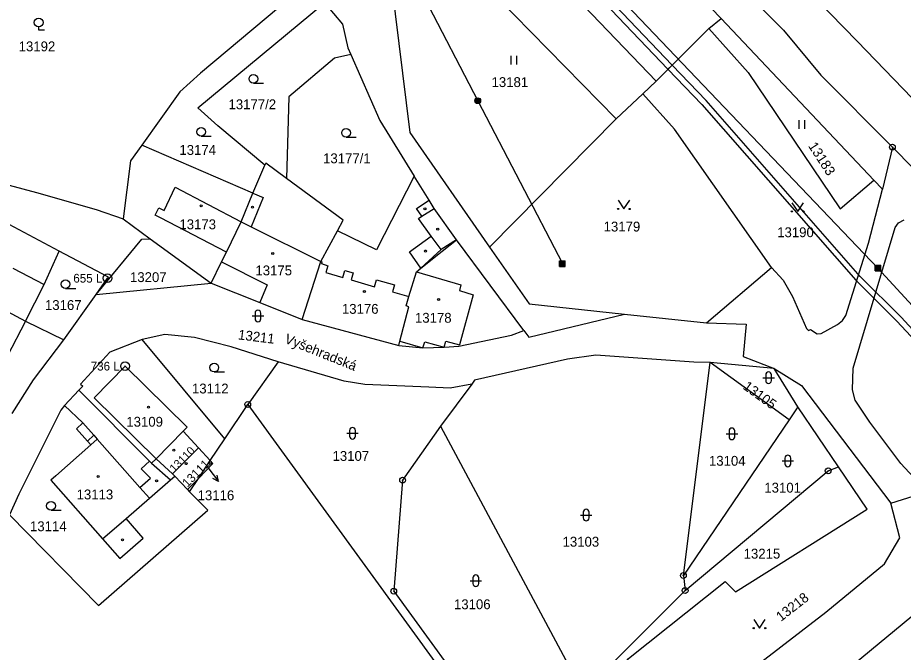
# Model space of a CAD drawing. Extents: x -821458 to -820266, y -1071458 to -1069826.
# Drawn here: x -820498 to -820345.1, y -1071261.9 to -1071152.4 of the extents above; entities that cross this region are included whole.
import ezdxf

# ---------------------------------------------------------------- set-up
doc = ezdxf.new("R2010")
doc.units = 0
for name, color, linetype in [('Vrstva 1', 7, 'Continuous'), ('Vrstva 13', 7, 'Continuous'), ('Vrstva 2', 7, 'Continuous'), ('Vrstva 3', 7, 'Continuous'), ('Vrstva 4', 7, 'Continuous'), ('Vrstva 5', 7, 'Continuous'), ('Vrstva 6', 7, 'Continuous'), ('Vrstva 7', 7, 'Continuous'), ('Vrstva 8', 7, 'Continuous')]:
    doc.layers.add(name, color=color, linetype=linetype)

msp = doc.modelspace()

# ---------------------------------------------------------------- linework, layer by layer
at = {"layer": 'Vrstva 1'}
for p, q in [((-820376.56, -1071152.47), (-820404.04, -1071123.96)), ((-820394.7, -1071169.8), (-820435.54, -1071128.19)), ((-820416.32, -1071133.58), (-820387.8, -1071163.3)), ((-820378.7, -1071154.2), (-820376.56, -1071152.47)), ((-820350.18, -1071180.42), (-820376.56, -1071152.47)), ((-820387.8, -1071163.3), (-820378.7, -1071154.2)), ((-820390.1, -1071165.5), (-820387.8, -1071163.3)), ((-820390.1, -1071165.5), (-820394.7, -1071169.8)), ((-820394.7, -1071169.8), (-820416.56, -1071192)), ((-820457.41, -1071182.67), (-820476.62, -1071174.38)), ((-820347, -1071174.7), (-820348.72, -1071181.96)), ((-820457.41, -1071182.67), (-820455.36, -1071177.84)), ((-820348.72, -1071181.96), (-820350.18, -1071180.42)), ((-820479.84, -1071187.11), (-820475.14, -1071190.53)), ((-820475.14, -1071190.53), (-820464.62, -1071198.17)), ((-820410.65, -1071206.34), (-820422.27, -1071190.7)), ((-820379.11, -1071205.04), (-820367.9, -1071195.5)), ((-820367.9, -1071195.5), (-820365.84, -1071197.65)), ((-820510.83, -1071197.24), (-820496.66, -1071204.76)), ((-820484.47, -1071200.14), (-820464.62, -1071198.17)), ((-820490.07, -1071207.98), (-820484.47, -1071200.14)), ((-820496.66, -1071204.76), (-820490.07, -1071207.98)), ((-820448.89, -1071204.48), (-820432.24, -1071208.93)), ((-820393.23, -1071203.55), (-820379.11, -1071205.04)), ((-820462.25, -1071225.04), (-820476.55, -1071207.91)), ((-820453.05, -1071211.75), (-820458.31, -1071219.13)), ((-820383.08, -1071248.67), (-820378.48, -1071211.88)), ((-820364.84, -1071221.76), (-820378.48, -1071211.88)), ((-820367.43, -1071212.95), (-820378.48, -1071211.88)), ((-820363.33, -1071219.52), (-820367.43, -1071212.95)), ((-820487.46, -1071216.64), (-820489.97, -1071219.33)), ((-820419.6, -1071215.61), (-820425.02, -1071222.9)), ((-820462.25, -1071225.04), (-820458.31, -1071219.13)), ((-820458.31, -1071219.13), (-820414.04, -1071279.95)), ((-820363.33, -1071219.52), (-820364.84, -1071221.76)), ((-820356.32, -1071229.9), (-820363.33, -1071219.52)), ((-820364.84, -1071221.76), (-820383.08, -1071248.67)), ((-820464.77, -1071228.82), (-820462.25, -1071225.04)), ((-820471.3, -1071231.09), (-820466.83, -1071226.61)), ((-820466.83, -1071226.61), (-820464.77, -1071228.82)), ((-820474.13, -1071228.51), (-820471.3, -1071231.09)), ((-820466.83, -1071231.91), (-820464.77, -1071228.82)), ((-820471.3, -1071231.09), (-820470.87, -1071231.52)), ((-820468.35, -1071234.19), (-820466.83, -1071231.91)), ((-820383.08, -1071248.67), (-820382.79, -1071251.27))]:
    msp.add_line(p, q, dxfattribs=at)
for points in [[(-820575.41, -1070898.25), (-820570.53, -1070910.66), (-820562.59, -1070929.03), (-820552.69, -1070946.67), (-820539.84, -1070967.11), (-820528.16, -1070983.62), (-820516.84, -1071000.47), (-820503.22, -1071015.12), (-820488.13, -1071031.13), (-820440.56, -1071079.73), (-820404.7, -1071115.79), (-820365.81, -1071154.53), (-820359.33, -1071162.29), (-820347, -1071174.7)], [(-820437.25, -1071144.25), (-820433.5, -1071146.49), (-820430.3, -1071172.18), (-820416.56, -1071192)], [(-820448.39, -1071146.76), (-820466.46, -1071161.95), (-820470.02, -1071165.17), (-820476.62, -1071174.38)], [(-820455.36, -1071177.84), (-820463.46, -1071171), (-820466.9, -1071167.9), (-820445.03, -1071149.78)], [(-820445.03, -1071149.78), (-820441.94, -1071153.46), (-820441.02, -1071157.59), (-820440.53, -1071158.71)], [(-820340.44, -1071169.52), (-820353.06, -1071156.4), (-820360.13, -1071149.18)], [(-820378.7, -1071154.2), (-820371.9, -1071161.8), (-820355.99, -1071185.37), (-820350.18, -1071180.42)], [(-820440.53, -1071158.71), (-820443.34, -1071159.32), (-820451.23, -1071166.02), (-820451.64, -1071180.1)], [(-820440.53, -1071158.71), (-820435.49, -1071170.13), (-820429.56, -1071179.71)], [(-820539.3, -1071159.45), (-820522.31, -1071172.09), (-820517.39, -1071175), (-820505.17, -1071179.75), (-820494.77, -1071182.54), (-820484.47, -1071185.46), (-820479.84, -1071187.11)], [(-820367.9, -1071195.5), (-820384.6, -1071171.6), (-820390.1, -1071165.5)], [(-820476.62, -1071174.38), (-820478.54, -1071177.06), (-820479.84, -1071187.11)], [(-820347, -1071174.7), (-820346.49, -1071175.21), (-820336.47, -1071185.46)], [(-820451.64, -1071180.1), (-820455.2, -1071177.47), (-820455.36, -1071177.84)], [(-820442.83, -1071189.15), (-820441.85, -1071187.34), (-820451.64, -1071180.1)], [(-820429.56, -1071179.71), (-820436.09, -1071192.46), (-820442.83, -1071189.15)], [(-820422.27, -1071190.7), (-820426.11, -1071185.29), (-820427.01, -1071183.84), (-820429.56, -1071179.71)], [(-820464.62, -1071198.17), (-820462.84, -1071194.51), (-820461.97, -1071192.83), (-820459.47, -1071187.61), (-820457.41, -1071182.67)], [(-820365.84, -1071197.65), (-820364.24, -1071200.52), (-820361.84, -1071206), (-820361.48, -1071206.37), (-820361.14, -1071206.21), (-820360, -1071206.96), (-820359.28, -1071206.87), (-820356.47, -1071205.32), (-820355.61, -1071204.65), (-820355.02, -1071203.75), (-820351.14, -1071191.31), (-820348.72, -1071181.96)], [(-820490.89, -1071192.65), (-820500.39, -1071187.63), (-820501.57, -1071187.01), (-820505.26, -1071185.93)], [(-820343.38, -1071231.68), (-820345.52, -1071229.33), (-820350.87, -1071222.17), (-820353.43, -1071218.41), (-820353.9, -1071216.58), (-820353.77, -1071212.85), (-820346.53, -1071188.58), (-820345.92, -1071187.79), (-820344.96, -1071187.27)], [(-820448.89, -1071204.48), (-820445.67, -1071194.43), (-820442.83, -1071189.15)], [(-820484.47, -1071200.14), (-820476.61, -1071190.6), (-820475.14, -1071190.53)], [(-820432.24, -1071208.93), (-820432.05, -1071208.22), (-820430.47, -1071202.26), (-820430.95, -1071202.12), (-820430.47, -1071200.52), (-820429.19, -1071196.22), (-820428.41, -1071195.6), (-820424.73, -1071192.67), (-820422.27, -1071190.7)], [(-820496.66, -1071204.76), (-820493.45, -1071198.44), (-820490.89, -1071192.65)], [(-820484.47, -1071200.14), (-820482.5, -1071197.34), (-820482.36, -1071197.15), (-820490.89, -1071192.65)], [(-820416.56, -1071192), (-820409.72, -1071201.74), (-820393.23, -1071203.55)], [(-820464.62, -1071198.17), (-820456.22, -1071201.54), (-820448.89, -1071204.48)], [(-820410.65, -1071206.34), (-820409.78, -1071207.51), (-820393.23, -1071203.55)], [(-820432.24, -1071208.93), (-820428.06, -1071209.38), (-820424.39, -1071209.25), (-820421.85, -1071209.06), (-820412.78, -1071207.15), (-820410.65, -1071206.34)], [(-820379.11, -1071205.04), (-820372.25, -1071205.26), (-820372.78, -1071210.85), (-820367.43, -1071212.95)], [(-820476.55, -1071207.91), (-820482.13, -1071210.12), (-820487.19, -1071215.63), (-820486.81, -1071215.95), (-820487.46, -1071216.64)], [(-820453.05, -1071211.75), (-820461.2, -1071209.17), (-820467.5, -1071207.56), (-820472.6, -1071207.05), (-820476.55, -1071207.91)], [(-820499.01, -1071220.67), (-820495.3, -1071214.89), (-820490.07, -1071207.98)], [(-820378.48, -1071211.88), (-820381.28, -1071211.81), (-820398.21, -1071210.6), (-820403.09, -1071211.33), (-820419.16, -1071214.95), (-820419.6, -1071215.61)], [(-820419.6, -1071215.61), (-820423.38, -1071216.29), (-820427.04, -1071216.16), (-820438.11, -1071215.68), (-820441.64, -1071215.11), (-820453.05, -1071211.75)], [(-820367.43, -1071212.95), (-820362.68, -1071215.85), (-820347.25, -1071236.15)], [(-820487.46, -1071216.64), (-820475.27, -1071228.92), (-820474.9, -1071229.29), (-820474.13, -1071228.51)], [(-820489.97, -1071219.33), (-820490.59, -1071220.12), (-820497.82, -1071234.6), (-820499.47, -1071238.21)], [(-820489.97, -1071219.33), (-820486.77, -1071222.33), (-820487.9, -1071223.33), (-820486, -1071225.47), (-820485.43, -1071226.12), (-820491.46, -1071231.44), (-820492.3, -1071232.18), (-820483.36, -1071242.35), (-820480.4, -1071245.73), (-820476.37, -1071242.19), (-820479.31, -1071238.83), (-820475.27, -1071235.32), (-820471.62, -1071232.17), (-820470.87, -1071231.52)], [(-820425.02, -1071222.9), (-820431.56, -1071232.21), (-820433.1, -1071251.37), (-820417.36, -1071272.99), (-820410.98, -1071267.78), (-820405.1, -1071274.59)], [(-820425.02, -1071222.9), (-820400.38, -1071268.87), (-820398.96, -1071271.52)], [(-820474.13, -1071228.51), (-820469.47, -1071223.77), (-820466.83, -1071226.61)], [(-820466.83, -1071231.91), (-820464.31, -1071229.31), (-820464.77, -1071228.82)], [(-820399.7, -1071273.16), (-820392.58, -1071262.99), (-820375.9, -1071249.7), (-820374.1, -1071251.5), (-820351.38, -1071237.19), (-820356.32, -1071229.9)], [(-820382.79, -1071251.27), (-820358.08, -1071230.59), (-820356.32, -1071229.9)], [(-820470.87, -1071231.52), (-820468.7, -1071233.83), (-820468.35, -1071234.19)], [(-820347.25, -1071236.15), (-820342.32, -1071234.63), (-820337.67, -1071234.87), (-820334.05, -1071232.87)], [(-820499.47, -1071238.21), (-820484.08, -1071253.85), (-820465.21, -1071237.36), (-820468.35, -1071234.19)], [(-820402.91, -1071290.65), (-820398.95, -1071286.93), (-820388.19, -1071277.72), (-820379.51, -1071270.89), (-820370.53, -1071264.24), (-820358.49, -1071254.97), (-820348.34, -1071246.63), (-820345.74, -1071242.13), (-820347.25, -1071236.15)], [(-820326.72, -1071239.67), (-820331.97, -1071245.01), (-820342.31, -1071254.65), (-820353.61, -1071263.96), (-820360.02, -1071268.97), (-820360.98, -1071270.3), (-820361.65, -1071272.32), (-820361.24, -1071273.9), (-820360.23, -1071275.23)], [(-820398.96, -1071271.52), (-820395.64, -1071264.1), (-820382.79, -1071251.27)]]:
    msp.add_lwpolyline(points, dxfattribs=at)
at = {"layer": 'Vrstva 13'}
msp.add_lwpolyline([(-820413.93, -1071131.71), (-820385.75, -1071161.25), (-820385.03, -1071160.53), (-820413.14, -1071131.09)], close=True, dxfattribs=at)
msp.add_lwpolyline([(-820341.51, -1071208.35), (-820345.51, -1071204.08), (-820352.56, -1071197.02), (-820379.18, -1071166.67), (-820385.03, -1071160.53), (-820385.75, -1071161.25), (-820379.92, -1071167.35), (-820353.3, -1071197.7), (-820346.23, -1071204.78), (-820342.21, -1071209.05)], dxfattribs=at)
at = {"layer": 'Vrstva 3'}
for p, q in [((-820494.41, -1071153.93), (-820494.41, -1071154.43)), ((-820494.41, -1071154.43), (-820493.41, -1071154.43)), ((-820412.85, -1071160.44), (-820412.85, -1071158.94)), ((-820411.85, -1071160.44), (-820411.85, -1071158.94)), ((-820457.34, -1071163.65), (-820455.59, -1071163.65)), ((-820363.1, -1071171.56), (-820363.1, -1071170.06)), ((-820362.1, -1071171.56), (-820362.1, -1071170.06)), ((-820466.35, -1071172.81), (-820464.6, -1071172.81)), ((-820441.34, -1071172.98), (-820439.59, -1071172.98)), ((-820489.76, -1071199.1), (-820488.01, -1071199.1)), ((-820457.04, -1071203.35), (-820457.04, -1071204.35)), ((-820456.04, -1071204.35), (-820456.04, -1071203.35)), ((-820457.54, -1071203.85), (-820455.54, -1071203.85)), ((-820464.09, -1071213.52), (-820462.34, -1071213.52)), ((-820368.88, -1071214.01), (-820368.88, -1071215.01)), ((-820367.88, -1071215.01), (-820367.88, -1071214.01)), ((-820369.38, -1071214.51), (-820367.38, -1071214.51)), ((-820441.22, -1071224.1), (-820439.22, -1071224.1)), ((-820440.72, -1071223.6), (-820440.72, -1071224.6)), ((-820439.72, -1071224.6), (-820439.72, -1071223.6)), ((-820375.71, -1071224.2), (-820373.71, -1071224.2)), ((-820375.21, -1071223.7), (-820375.21, -1071224.7)), ((-820374.21, -1071224.7), (-820374.21, -1071223.7)), ((-820366.05, -1071228.88), (-820364.05, -1071228.88)), ((-820365.55, -1071228.38), (-820365.55, -1071229.38)), ((-820364.55, -1071229.38), (-820364.55, -1071228.38)), ((-820492.28, -1071237.39), (-820490.53, -1071237.39)), ((-820400.88, -1071238.23), (-820398.88, -1071238.23)), ((-820400.38, -1071237.73), (-820400.38, -1071238.73)), ((-820399.38, -1071238.73), (-820399.38, -1071237.73)), ((-820419.42, -1071249.06), (-820419.42, -1071250.06)), ((-820418.42, -1071250.06), (-820418.42, -1071249.06)), ((-820419.92, -1071249.56), (-820417.92, -1071249.56))]:
    msp.add_line(p, q, dxfattribs=at)
for points in [[(-820394.36, -1071183.88), (-820393.36, -1071185.38), (-820392.36, -1071183.88)], [(-820364.35, -1071184.3), (-820363.35, -1071185.8), (-820362.35, -1071184.3)], [(-820370.94, -1071256.24), (-820369.94, -1071257.74), (-820368.94, -1071256.24)]]:
    msp.add_lwpolyline(points, dxfattribs=at)
for centre, radius in [((-820494.41, -1071153.18), 0.75), ((-820457.34, -1071162.9), 0.75), ((-820466.35, -1071172.06), 0.75), ((-820441.34, -1071172.23), 0.75), ((-820394.36, -1071185.38), 0.1), ((-820392.36, -1071185.38), 0.1), ((-820364.35, -1071185.8), 0.1), ((-820362.35, -1071185.8), 0.1), ((-820489.76, -1071198.35), 0.75), ((-820464.09, -1071212.77), 0.75), ((-820492.28, -1071236.64), 0.75), ((-820370.94, -1071257.74), 0.1), ((-820368.94, -1071257.74), 0.1)]:
    msp.add_circle(centre, radius, dxfattribs=at)
for centre, start, end in [((-820456.54, -1071203.35), 0, 180), ((-820456.54, -1071204.35), 180, 359.9879), ((-820368.38, -1071214.01), 0, 180), ((-820368.38, -1071215.01), 180, 359.9879), ((-820440.22, -1071223.6), 0, 180), ((-820374.71, -1071223.7), 0, 180), ((-820440.22, -1071224.6), 180, 359.9879), ((-820374.71, -1071224.7), 180, 359.9879), ((-820365.05, -1071228.38), 0, 180), ((-820365.05, -1071229.38), 180, 359.9879), ((-820399.88, -1071237.73), 0, 180), ((-820399.88, -1071238.73), 180, 359.9879), ((-820418.92, -1071249.06), 0, 180), ((-820418.92, -1071250.06), 180, 359.9879)]:
    msp.add_arc(centre, 0.5, start, end, dxfattribs=at)
at = {"layer": 'Vrstva 4'}
for p, q in [((-820472.76, -1071185.64), (-820470.82, -1071181.61)), ((-820470.82, -1071181.61), (-820459.47, -1071187.61)), ((-820455.64, -1071183.41), (-820457.74, -1071188.47)), ((-820457.41, -1071182.67), (-820455.64, -1071183.41)), ((-820429.17, -1071185.31), (-820427.01, -1071183.84)), ((-820474.27, -1071186.47), (-820473.66, -1071185.2)), ((-820473.37, -1071186.9), (-820474.27, -1071186.47)), ((-820473.66, -1071185.2), (-820472.76, -1071185.64)), ((-820428.23, -1071186.62), (-820429.17, -1071185.31)), ((-820428.23, -1071186.62), (-820426.11, -1071185.29)), ((-820461.97, -1071192.83), (-820473.37, -1071186.9)), ((-820459.47, -1071187.61), (-820457.74, -1071188.47)), ((-820428.81, -1071187.03), (-820428.23, -1071186.62)), ((-820426.62, -1071190.06), (-820428.81, -1071187.03)), ((-820457.74, -1071188.47), (-820445.67, -1071194.43)), ((-820430.38, -1071192.77), (-820426.62, -1071190.06)), ((-820424.93, -1071192.4), (-820426.62, -1071190.06)), ((-820422.27, -1071190.7), (-820424.93, -1071192.4)), ((-820424.93, -1071192.4), (-820428.41, -1071195.6)), ((-820428.41, -1071195.6), (-820430.38, -1071192.77)), ((-820498.88, -1071195.6), (-820493.45, -1071198.44)), ((-820462.84, -1071194.51), (-820454.94, -1071198.48)), ((-820445.67, -1071194.43), (-820445.49, -1071194.49)), ((-820445.49, -1071194.49), (-820445.59, -1071194.82)), ((-820445.59, -1071194.82), (-820444.48, -1071195.17)), ((-820444.48, -1071195.17), (-820444.85, -1071196.35)), ((-820444.85, -1071196.35), (-820441.87, -1071197.21)), ((-820441.87, -1071197.21), (-820441.53, -1071196.01)), ((-820441.53, -1071196.01), (-820440.11, -1071196.42)), ((-820440.11, -1071196.42), (-820440.46, -1071197.62)), ((-820429.19, -1071196.22), (-820421.54, -1071198.49)), ((-820454.94, -1071198.48), (-820456.22, -1071201.54)), ((-820440.46, -1071197.62), (-820436.42, -1071198.8)), ((-820436.42, -1071198.8), (-820436.07, -1071197.6)), ((-820436.07, -1071197.6), (-820432.96, -1071198.5)), ((-820432.96, -1071198.5), (-820433.31, -1071199.7)), ((-820421.54, -1071198.49), (-820421.77, -1071199.43)), ((-820433.31, -1071199.7), (-820430.47, -1071200.52)), ((-820421.77, -1071199.43), (-820419.41, -1071200.21)), ((-820419.41, -1071200.21), (-820421.76, -1071208.86)), ((-820496.66, -1071204.76), (-820499.85, -1071210.87)), ((-820432.05, -1071208.22), (-820428.06, -1071209.38)), ((-820428.06, -1071209.38), (-820427.76, -1071208.32)), ((-820427.76, -1071208.32), (-820424.39, -1071209.25)), ((-820424.39, -1071209.25), (-820424.08, -1071208.19)), ((-820424.08, -1071208.19), (-820421.76, -1071208.86)), ((-820484.85, -1071217.96), (-820479.5, -1071212.52)), ((-820479.5, -1071212.52), (-820468.76, -1071223.06)), ((-820484.85, -1071217.96), (-820474.13, -1071228.51)), ((-820486.77, -1071222.33), (-820484.87, -1071224.44)), ((-820468.76, -1071223.06), (-820469.47, -1071223.77)), ((-820484.87, -1071224.44), (-820486, -1071225.47)), ((-820484.87, -1071224.44), (-820484.29, -1071225.11)), ((-820485.43, -1071226.12), (-820484.29, -1071225.11)), ((-820484.29, -1071225.11), (-820476.92, -1071233.45)), ((-820476.7, -1071230.22), (-820475.27, -1071228.92)), ((-820474.9, -1071229.29), (-820471.62, -1071232.17)), ((-820475.12, -1071231.85), (-820476.7, -1071230.22)), ((-820476.92, -1071233.45), (-820475.12, -1071231.85)), ((-820468.7, -1071233.83), (-820466.83, -1071231.91)), ((-820476.92, -1071233.45), (-820475.27, -1071235.32)), ((-820483.36, -1071242.35), (-820479.31, -1071238.83))]:
    msp.add_line(p, q, dxfattribs=at)
at = {"layer": 'Vrstva 5'}
for centre in [(-820466.37, -1071184.82), (-820457.48, -1071185.06), (-820427.71, -1071185.35), (-820425.51, -1071188.85), (-820427.62, -1071192.64), (-820454, -1071193.06), (-820438.17, -1071199.62), (-820425.35, -1071201.01), (-820475.43, -1071219.58), (-820471.08, -1071227.01), (-820468.96, -1071229.35), (-820464.8, -1071229.33), (-820484.15, -1071231.55), (-820474.04, -1071232.32), (-820479.94, -1071242.5)]:
    msp.add_circle(centre, 0.175, dxfattribs=at)
at = {"layer": 'Vrstva 6'}
for p, q in [((-820436.58, -1071104.39), (-820349.5, -1071195.59)), ((-820435.72, -1071133.7), (-820418.6, -1071166.69)), ((-820418.6, -1071166.69), (-820403.98, -1071194.82)), ((-820404.48, -1071194.32), (-820403.48, -1071194.32)), ((-820404.48, -1071195.32), (-820404.48, -1071194.32)), ((-820404.48, -1071194.52), (-820403.48, -1071194.52)), ((-820404.48, -1071194.72), (-820403.48, -1071194.72)), ((-820404.48, -1071194.92), (-820403.48, -1071194.92)), ((-820404.48, -1071195.12), (-820403.48, -1071195.12)), ((-820404.48, -1071195.32), (-820403.48, -1071195.32)), ((-820404.28, -1071195.32), (-820404.28, -1071194.32)), ((-820404.08, -1071195.32), (-820404.08, -1071194.32)), ((-820403.88, -1071195.32), (-820403.88, -1071194.32)), ((-820403.68, -1071195.32), (-820403.68, -1071194.32)), ((-820403.48, -1071195.32), (-820403.48, -1071194.32)), ((-820350, -1071195.09), (-820349, -1071195.09)), ((-820350, -1071196.09), (-820350, -1071195.09)), ((-820350, -1071195.29), (-820349, -1071195.29)), ((-820350, -1071195.49), (-820349, -1071195.49)), ((-820350, -1071195.69), (-820349, -1071195.69)), ((-820349.8, -1071196.09), (-820349.8, -1071195.09)), ((-820349.6, -1071196.09), (-820349.6, -1071195.09)), ((-820349.5, -1071195.59), (-820296.89, -1071253.29)), ((-820349.4, -1071196.09), (-820349.4, -1071195.09)), ((-820349.2, -1071196.09), (-820349.2, -1071195.09)), ((-820349, -1071196.09), (-820349, -1071195.09)), ((-820350, -1071195.89), (-820349, -1071195.89)), ((-820350, -1071196.09), (-820349, -1071196.09))]:
    msp.add_line(p, q, dxfattribs=at)
for radius in [0.5, 0.4, 0.3, 0.2, 0.1]:
    msp.add_circle((-820418.6, -1071166.69), radius, dxfattribs=at)
at = {"layer": 'Vrstva 7'}
for p, q in [((-820465.2, -1071230.04), (-820463.35, -1071232.41)), ((-820463.35, -1071232.41), (-820464.36, -1071231.92)), ((-820463.35, -1071232.41), (-820463.57, -1071231.31))]:
    msp.add_line(p, q, dxfattribs=at)
at = {"layer": 'Vrstva 8'}
for centre, radius in [((-820347, -1071174.7), 0.5), ((-820347, -1071174.7), 0.0303), ((-820482.5, -1071197.34), 0.75), ((-820482.5, -1071197.34), 0.03), ((-820479.5, -1071212.52), 0.75), ((-820479.5, -1071212.52), 0.03), ((-820458.31, -1071219.13), 0.5), ((-820458.31, -1071219.13), 0.0303), ((-820358.08, -1071230.59), 0.5), ((-820358.08, -1071230.59), 0.0303), ((-820431.56, -1071232.21), 0.5), ((-820431.56, -1071232.21), 0.0303), ((-820383.08, -1071248.67), 0.5), ((-820383.08, -1071248.67), 0.0303), ((-820433.1, -1071251.37), 0.5), ((-820433.1, -1071251.37), 0.0303), ((-820382.79, -1071251.27), 0.5), ((-820382.79, -1071251.27), 0.0303)]:
    msp.add_circle(centre, radius, dxfattribs=at)

# ---------------------------------------------------------------- texts
at = {"layer": 'Vrstva 2'}
for s, p in [('13192', (-820497.86, -1071158.16)), ('13181', (-820416.21, -1071164.33)), ('13177/2', (-820461.63, -1071168.16)), ('13174', (-820470.11, -1071176.04)), ('13177/1', (-820445.3, -1071177.49)), ('13173', (-820470.11, -1071188.88)), ('13179', (-820396.86, -1071189.27)), ('13190', (-820366.89, -1071190.25)), ('13175', (-820456.98, -1071196.84)), ('13207', (-820478.64, -1071198)), ('13167', (-820493.32, -1071202.82)), ('13176', (-820442.05, -1071203.48)), ('13178', (-820429.43, -1071205.02)), ('13112', (-820467.94, -1071217.23)), ('13109', (-820479.27, -1071222.97)), ('13107', (-820443.67, -1071228.87)), ('13104', (-820378.67, -1071229.71)), ('13113', (-820487.86, -1071235.52)), ('13116', (-820466.96, -1071235.66)), ('13101', (-820369.11, -1071234.35)), ('13114', (-820495.91, -1071241.01)), ('13103', (-820403.95, -1071243.68)), ('13215', (-820372.68, -1071245.74)), ('13106', (-820422.7, -1071254.48))]:
    msp.add_text(s, height=1.7, dxfattribs=at).set_placement(p)
for s, height, rotation, p in [('13183', 1.7, 303, (-820361.6, -1071174.5)), ('13211', 1.7, 353, (-820460.04, -1071207.89)), ('13105', 1.7, 324, (-820372.92, -1071216.35)), ('13110', 1.4, 45, (-820470.98, -1071230.94)), ('13111', 1.5, 45, (-820468.72, -1071233.51)), ('13218', 1.7, 38, (-820366.25, -1071256.69))]:
    msp.add_text(s, height=height, rotation=rotation, dxfattribs=at).set_placement(p)
at = {"layer": 'Vrstva 7'}
msp.add_text('Vyšehradská', height=1.7, rotation=338, dxfattribs=at).set_placement((-820452.09, -1071208.44))
at = {"layer": 'Vrstva 8'}
for s, p in [('655 L', (-820488.43, -1071198.09)), ('736 L', (-820485.43, -1071213.27))]:
    msp.add_text(s, height=1.5, dxfattribs=at).set_placement(p)

doc.saveas('drawing.dxf')
